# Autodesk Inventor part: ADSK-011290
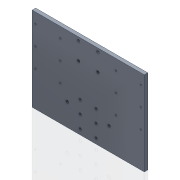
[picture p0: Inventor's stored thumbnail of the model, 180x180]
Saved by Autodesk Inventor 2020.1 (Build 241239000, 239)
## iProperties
Created: 1999-11
Part Number: ADSK-011290
Material: Pearson Aluminium
Document SubType Name: Modeling
Designer: sspink
Density: 2.71 g/cm^3
Appearance: Pearson-Aluminum
Mass: 4148.31 g
Surface Area: 2699.26 cm^2
Volume: 1530.74 cm^3
Control State: 0
Master: False
Checked Out: False
Shininess: 35.0
Length Units: 11269
Angle Units: 11279
Time Units: 11290
Mass Units: 11283
Length Display Precision: 3
Angle Display Precision: 2
Compacted: True
Dimensions: 406x305x12,5 mm
Mass: 4,148 kg
DocNumber: ADSK-011290.ipt
Folder: 01 - Themengebiete\Simplification\01 - Packaging machine\
VDS_Category: 3D Komponenten
Density: 2.71
Volumn: 1554.780541199509
Area: 2703.381883141726
PropertySet Name: Model Information
Author: sspink
Revision Number: -
Title: base plate
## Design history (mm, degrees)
node "Extrusion1" dims "d2" = 12.5, "d3" = 0
  sketch "Sketch1"
    geometry: L1 (-203, 152.5)-(203, 152.5); L2 (203, 152.5)-(203, -152.5); L3 (203, -152.5)-(-203, -152.5); L4 (-203, -152.5)-(-203, 152.5); 3 further points
    constraints: 8 end point, 2 midpoint, 2 parallel, 1 horizontal, 1 horizontal alignment, 1 perpendicular, 1 vertical alignment
    dimensions: "d0" = 406 distance of L1.start L1.end; "d1" = 305 distance of L3.end L1.start
node "Hole2" dims "d18" = 5.5, "d19" = 9.525, "d20" = 6.35, "d21" = 60 deg, "d22" = 19.05, "d23" = 118 deg, "d80" = 6
  sketch "Sketch3"
    geometry: L1 (-203, 152.5)-(203, 152.5) reference; L2 (-191, 114.5)-(-101, 114.5); L3 (-101, 114.5)-(-101, -25.5); L4 (-101, -25.5)-(-191, -25.5); L5 (-191, -25.5)-(-191, 114.5); L6 (0, 152.5)-(0, -152.5); L7 (203, -152.5)-(-203, -152.5) reference; 6 further points
    constraints: 10 end point, 5 midpoint, 3 coincident, 2 parallel, 1 horizontal, 1 perpendicular, 1 vertical
    dimensions: "d17" = 38 distance from line of L2.start L1; "d77" = 90 distance of L2.start L2.end; "d78" = 140 distance of L2.end L3.end; "d79" = 146 distance from line of L6 point (-146, 114.5)
workplane "Work Plane1"
node "Hole4" dims "d49" = 10, "d50" = 9.525, "d51" = 6.35, "d52" = 60 deg, "d53" = 19.05, "d54" = 118 deg, "d82" = 6
  sketch "Sketch5"
    geometry: L1 (203, -152.5)-(-203, -152.5) reference; L2 (-76, -71.5)-(76, -71.5); 2 further points
    constraints: 2 end point, 2 midpoint, 1 horizontal, 1 vertical alignment
    dimensions: "d47" = 81 distance from line of L1 L2.end; "d81" = 152 distance of L2.start L2.end
node "Hole5" dims "d55" = 10, "d56" = 9.525, "d57" = 6.35, "d58" = 60 deg, "d59" = 19.05, "d60" = 118 deg, "d84" = 6
  sketch "Sketch6"
    geometry: L1 (-203, 152.5)-(203, 152.5) reference; L2 (203, -152.5)-(-203, -152.5) reference; L3 (0, 152.5)-(0, -152.5); 4 further points
    constraints: 2 end point, 2 horizontal alignment, 2 midpoint, 2 vertical alignment
    dimensions: "d63" = 12.5 distance from line of point (-35, 140) L1; "d75" = 70 distance of point (35, 140) point (-35, 140); "d76" = 35 distance from line of L3 point (-35, 140) (= 0.5 x d75); "d83" = 63.5 distance of point (-35, 76.5) point (-35, 140)
workplane "Arbeitsebene2"
mirror "Spiegeln1"
node "Hole6" dims "d69" = 9, "d70" = 19, "d71" = 6.35, "d72" = 90 deg, "d73" = 19.05, "d74" = 118 deg, "d87" = 6
  sketch "Sketch7"
    geometry: L1 (203, -152.5)-(-203, -152.5) reference; L2 (-28.75, -41.5)-(-28.75, -133.5); L3 (28.75, -41.5)-(28.75, -133.5); L4 (-28.75, -41.5)-(28.75, -41.5); L5 (28.75, -133.5)-(-28.75, -133.5); 4 further points
    constraints: 8 end point, 4 midpoint, 3 vertical alignment, 2 horizontal alignment, 1 horizontal, 1 parallel
    dimensions: "d68" = 19 distance from line of L2.end L1; "d85" = 92 distance of L3.start L3.end; "d86" = 57.5 distance of L2.start L3.start
node "Solide1"
node "Corps solides"
node "Corps surfaciques"
workplane "Arbeitsebene3"
other parameters: "d15" = 25.4, "d44" = 196.85
